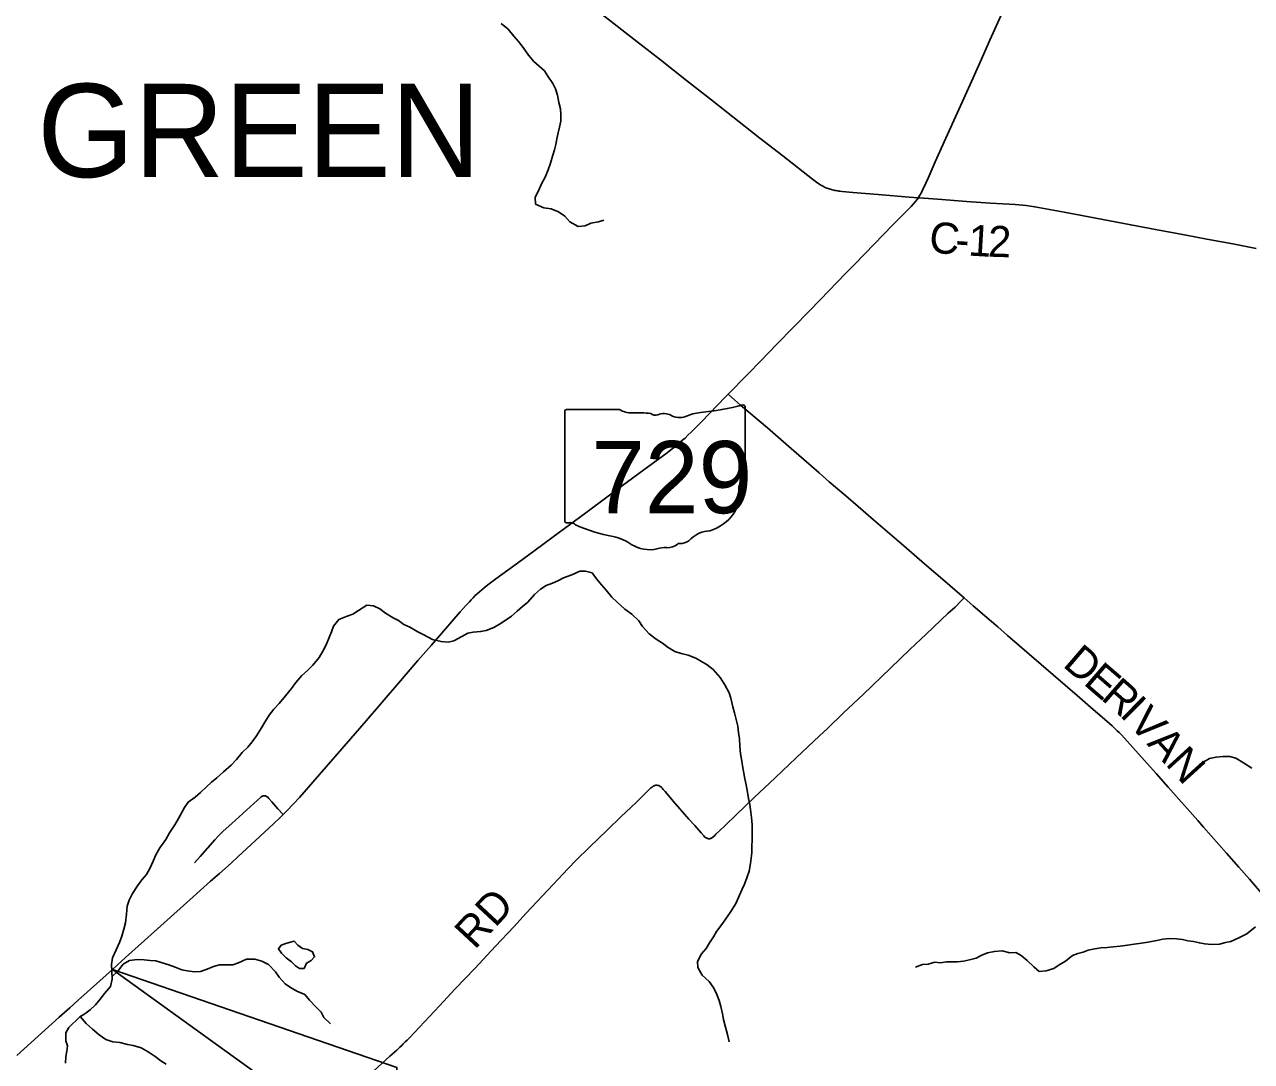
# Model space of a CAD drawing. Extents: x 0 to 34, y 0 to 22.
# Drawn here: x 25.971 to 28.213, y 15.082 to 16.977 of the extents above; entities that cross this region are included whole.
import ezdxf

# ---------------------------------------------------------------- set-up
doc = ezdxf.new("R2010")
doc.units = 0
for name, color, linetype in [('GM_X_County_Road', 7, 'Continuous'), ('GM_X_County_Road_Text', 7, 'Continuous'), ('GM_X_Minor_Lake', 7, 'Continuous'), ('GM_X_Minor_River', 7, 'Continuous'), ('GM_X_State_Location', 7, 'Continuous'), ('GM_X_State_Route', 7, 'Continuous'), ('GM_X_State_Shield', 7, 'Continuous'), ('GM_X_Township_Road', 7, 'Continuous'), ('GM_X_Township_Road_Text', 7, 'Continuous'), ('GM_X_Township_Text', 7, 'Continuous'), ('SH_Text', 7, 'Continuous')]:
    doc.layers.add(name, color=color, linetype=linetype)

msp = doc.modelspace()

# ---------------------------------------------------------------- linework, layer by layer
at = {"layer": 'GM_X_County_Road'}
for points in [[(27.6045, 16.66), (27.5878, 16.6613), (27.5315, 16.6661), (27.485, 16.67), (27.4654, 16.6718), (27.4615, 16.6722), (27.4595, 16.6725), (27.4577, 16.6727), (27.4548, 16.6732), (27.4525, 16.6736), (27.4519, 16.6737), (27.4504, 16.674), (27.4494, 16.6742), (27.4472, 16.6747), (27.4458, 16.6751), (27.4438, 16.6757), (27.4417, 16.6764), (27.4402, 16.6769), (27.4378, 16.6778), (27.4343, 16.6792), (27.4318, 16.6804), (27.4305, 16.6811), (27.4284, 16.6823), (27.4274, 16.6828), (27.426, 16.6837), (27.4211, 16.6871), (27.4112, 16.6944), (27.3568, 16.7369), (27.315, 16.7692), (27.2657, 16.8079), (27.2247, 16.8403), (27.1813, 16.8746), (27.1333, 16.912), (27.1148, 16.9267), (27.0957, 16.9416), (27.0157, 17.0038)], [(28.222, 16.5677), (28.1792, 16.5759), (28.1322, 16.5847), (28.0943, 16.5918), (28.0381, 16.6022), (27.9929, 16.6107), (27.9386, 16.6211), (27.8715, 16.6338), (27.8177, 16.6437), (27.8017, 16.6461), (27.7818, 16.648), (27.7365, 16.6506), (27.6925, 16.6535), (27.6479, 16.6568), (27.607, 16.6598), (27.6045, 16.66)], [(27.6882, 15.9292), (27.6805, 15.9359), (27.6533, 15.9596), (27.6161, 15.9916), (27.5785, 16.0242), (27.5525, 16.0463), (27.5229, 16.0718), (27.4946, 16.0961), (27.4721, 16.1157), (27.4419, 16.1415), (27.4232, 16.1579), (27.4049, 16.1739), (27.3678, 16.2059), (27.3288, 16.2396), (27.2795, 16.2815), (27.2632, 16.2958), (27.257, 16.3011)], [(28.2357, 15.3855), (28.2096, 15.4154), (28.1901, 15.4372), (28.1678, 15.4631), (28.1259, 15.5106), (28.1152, 15.5227), (28.0613, 15.5837), (28.0393, 15.6082), (27.9969, 15.6561), (27.9814, 15.6731), (27.9766, 15.6782), (27.9719, 15.6831), (27.9683, 15.6866), (27.9639, 15.6909), (27.9588, 15.6955), (27.9542, 15.6997), (27.9195, 15.7298), (27.8951, 15.751), (27.807, 15.8267), (27.7895, 15.8417), (27.7674, 15.8607), (27.7498, 15.8764), (27.7384, 15.8861), (27.7049, 15.9148), (27.6882, 15.9292)]]:
    msp.add_lwpolyline(points, dxfattribs=at)
at = {"layer": 'GM_X_Minor_Lake'}
for points in [[(26.4925, 15.285), (26.4889, 15.2867), (26.4794, 15.2887), (26.4707, 15.2945), (26.464, 15.3018), (26.4548, 15.2996), (26.4491, 15.2977), (26.4404, 15.2948), (26.4354, 15.288), (26.441, 15.28), (26.4493, 15.2715), (26.4595, 15.2646)], [(26.4595, 15.2646), (26.4666, 15.257), (26.4741, 15.252), (26.4821, 15.2523), (26.4867, 15.2617), (26.4951, 15.2669), (26.5013, 15.2733), (26.4979, 15.2825), (26.4925, 15.285)]]:
    msp.add_lwpolyline(points, dxfattribs=at)
at = {"layer": 'GM_X_Minor_River'}
for points in [[(26.8426, 16.9788), (26.8551, 16.968), (26.8656, 16.9554), (26.8738, 16.9454), (26.8828, 16.9347), (26.8926, 16.9209), (26.9023, 16.909), (26.9213, 16.892)], [(26.9213, 16.892), (26.9276, 16.8826), (26.937, 16.8692), (26.9414, 16.8593), (26.9455, 16.8475), (26.9477, 16.8345), (26.9506, 16.8228), (26.9516, 16.8121), (26.9512, 16.8004), (26.9492, 16.7894), (26.9464, 16.7788), (26.9444, 16.7678), (26.942, 16.7576), (26.9397, 16.7477), (26.9369, 16.7379), (26.9326, 16.7235), (26.928, 16.711), (26.9229, 16.6978), (26.9163, 16.6857), (26.9105, 16.6728), (26.9047, 16.6615), (26.9054, 16.6486), (26.9205, 16.642), (26.9338, 16.64), (26.9474, 16.6342), (26.9587, 16.6265), (26.9677, 16.6161), (26.9828, 16.6076), (26.9961, 16.6087), (27.0064, 16.6135), (27.0204, 16.6164), (27.03, 16.6194)], [(26.4107, 15.7023), (26.4184, 15.7151), (26.4272, 15.726), (26.4368, 15.7362), (26.4483, 15.7501), (26.4591, 15.7637), (26.4671, 15.7746), (26.4782, 15.7874), (26.4882, 15.7965), (26.4982, 15.8062), (26.51, 15.8202), (26.5166, 15.8319), (26.5224, 15.8432), (26.5278, 15.8568), (26.5321, 15.8674), (26.536, 15.8776), (26.5456, 15.8897), (26.5608, 15.8956), (26.5715, 15.8997), (26.5814, 15.9061), (26.5967, 15.9158), (26.6092, 15.9149), (26.6205, 15.9091), (26.6311, 15.9015), (26.645, 15.8926), (26.6548, 15.888), (26.6646, 15.8803), (26.6756, 15.8756), (26.6899, 15.8675), (26.7001, 15.8625), (26.7171, 15.8532), (26.7327, 15.8493), (26.7456, 15.8484), (26.7558, 15.851), (26.7703, 15.8588), (26.7814, 15.8648), (26.7909, 15.8666), (26.8049, 15.8676), (26.8152, 15.8694), (26.8289, 15.8754), (26.8392, 15.881), (26.8499, 15.8877), (26.861, 15.896), (26.8717, 15.905), (26.8816, 15.9132), (26.8912, 15.9215), (26.9034, 15.9351), (26.9141, 15.9452), (26.9245, 15.9519), (26.9363, 15.9564), (26.9458, 15.9605), (26.9565, 15.9657), (26.9713, 15.9716), (26.9862, 15.978), (26.9964, 15.9779), (27.0085, 15.9747), (27.0168, 15.964), (27.0258, 15.9533), (27.034, 15.9434), (27.0449, 15.9307), (27.0543, 15.9212), (27.0686, 15.9089), (27.0814, 15.8993), (27.0942, 15.887), (27.1006, 15.8767), (27.1126, 15.8637), (27.1254, 15.8541), (27.1371, 15.8468), (27.1477, 15.8384), (27.1598, 15.831), (27.1715, 15.8275), (27.1844, 15.8244), (27.1983, 15.8189), (27.2082, 15.8128), (27.2187, 15.807), (27.2297, 15.7981), (27.2424, 15.784), (27.2514, 15.7702), (27.2589, 15.7558), (27.2618, 15.7462), (27.2658, 15.7299), (27.2688, 15.7192), (27.2724, 15.7048), (27.2746, 15.6949), (27.276, 15.6835), (27.2778, 15.6717), (27.2788, 15.6584), (27.2799, 15.6444), (27.282, 15.6307), (27.2842, 15.6189), (27.2856, 15.609), (27.2874, 15.5984), (27.29, 15.5877), (27.2925, 15.5744), (27.2943, 15.5626), (27.2965, 15.552), (27.2983, 15.5425), (27.3, 15.528), (27.3011, 15.5144), (27.3013, 15.5015), (27.3012, 15.4886)], [(26.0464, 15.079), (26.0466, 15.0915), (26.0485, 15.1013), (26.0498, 15.1108), (26.0468, 15.1203), (26.0466, 15.1347), (26.0524, 15.1446), (26.0723, 15.1641), (26.0818, 15.1693), (26.0914, 15.1768), (26.1009, 15.1859), (26.1094, 15.196), (26.1178, 15.2062), (26.1282, 15.219), (26.1317, 15.2327), (26.1307, 15.2478), (26.1301, 15.2596), (26.1324, 15.2717), (26.1386, 15.2861), (26.1448, 15.2997), (26.1491, 15.3111), (26.153, 15.3243), (26.1558, 15.3357), (26.1574, 15.3516), (26.1591, 15.366), (26.1626, 15.377), (26.1688, 15.3894), (26.1776, 15.403), (26.1857, 15.414), (26.1942, 15.4238), (26.2003, 15.4351), (26.2065, 15.4483), (26.2112, 15.46), (26.2185, 15.4729), (26.2293, 15.4876), (26.2362, 15.4997), (26.2462, 15.5144), (26.2528, 15.5261), (26.2636, 15.5465), (26.2701, 15.5563), (26.2831, 15.5649), (26.2927, 15.5739), (26.303, 15.5833), (26.3129, 15.5923), (26.3229, 15.6006), (26.3347, 15.6115), (26.3489, 15.6239), (26.3585, 15.6337), (26.3688, 15.6469), (26.3795, 15.6563), (26.3876, 15.6661), (26.3953, 15.6774), (26.4041, 15.6921), (26.4107, 15.7023)], [(28.2142, 15.6181), (28.1991, 15.6278), (28.1852, 15.6366), (28.1742, 15.6394), (28.1617, 15.6395), (28.1487, 15.6385), (28.137, 15.6355), (28.1232, 15.6281)], [(27.3012, 15.4886), (27.3007, 15.4741), (27.3002, 15.4635), (27.2994, 15.4537), (27.2981, 15.4438), (27.2954, 15.4298), (27.2911, 15.4177), (27.2868, 15.4063), (27.2821, 15.3957), (27.276, 15.3821), (27.2713, 15.3708), (27.2632, 15.358), (27.2544, 15.3448), (27.2436, 15.3304), (27.2359, 15.3199), (27.2301, 15.3101), (27.2232, 15.2991), (27.2167, 15.2889), (27.2086, 15.2787), (27.2009, 15.2652), (27.2016, 15.2541), (27.2098, 15.24), (27.2226, 15.2285), (27.2297, 15.2182), (27.2353, 15.2079), (27.2408, 15.1938), (27.2438, 15.1828), (27.2471, 15.1695), (27.2489, 15.1592), (27.2522, 15.1451), (27.2558, 15.1318), (27.2588, 15.1181)], [(28.221, 15.3285), (28.205, 15.3157), (28.1905, 15.3083), (28.1757, 15.3016), (28.1661, 15.2994), (28.1551, 15.2964), (28.1407, 15.2958), (28.1282, 15.2971), (28.1183, 15.299), (28.1077, 15.3014), (28.0975, 15.303), (28.0877, 15.305), (28.0763, 15.3063), (28.0634, 15.3071), (28.0516, 15.3057), (28.0406, 15.3035), (28.0242, 15.3003), (28.0128, 15.2985), (27.9992, 15.2967), (27.987, 15.2949), (27.9737, 15.2931), (27.9608, 15.2917)], [(27.9608, 15.2917), (27.9498, 15.2907), (27.9384, 15.2897), (27.9274, 15.2879), (27.9152, 15.2857), (27.9057, 15.282), (27.8962, 15.2794), (27.8867, 15.2757), (27.8737, 15.2656), (27.8618, 15.2588), (27.8523, 15.2521), (27.8382, 15.2477), (27.8257, 15.2466), (27.8155, 15.2555), (27.8035, 15.2666), (27.7929, 15.2758), (27.7827, 15.2812), (27.7717, 15.2809), (27.7581, 15.2844), (27.7437, 15.2834), (27.7308, 15.2809), (27.7208, 15.2764), (27.7106, 15.2708), (27.698, 15.2679), (27.687, 15.2653), (27.6763, 15.2643), (27.6657, 15.2644), (27.6562, 15.2641), (27.6452, 15.2623), (27.6346, 15.2635), (27.6224, 15.2599), (27.6125, 15.2592), (27.5996, 15.2547)], [(26.1314, 15.2375), (26.1421, 15.247), (26.1517, 15.2602), (26.1631, 15.2665), (26.1776, 15.2687), (26.1897, 15.2682), (26.2011, 15.2669), (26.2113, 15.2661), (26.2212, 15.2633), (26.2351, 15.2587), (26.2465, 15.2548), (26.2586, 15.2497), (26.2688, 15.2477), (26.2821, 15.2461), (26.2927, 15.2464), (26.3053, 15.2508), (26.3167, 15.256), (26.3277, 15.259), (26.3387, 15.2589), (26.352, 15.2591), (26.3623, 15.2628), (26.3772, 15.2691), (26.3923, 15.269), (26.4048, 15.2655), (26.4169, 15.2593), (26.4301, 15.2463), (26.4368, 15.2363), (26.4477, 15.2241), (26.4575, 15.2172), (26.4688, 15.211), (26.4836, 15.2048), (26.4922, 15.1945), (26.5042, 15.1818), (26.5136, 15.1723), (26.5185, 15.1627), (26.5305, 15.1512)], [(26.0731, 15.1646), (26.0843, 15.1515), (26.0956, 15.1411), (26.108, 15.1308), (26.1201, 15.1223), (26.1326, 15.1184), (26.1458, 15.1171), (26.1595, 15.1136), (26.1697, 15.1112), (26.1844, 15.1073), (26.1973, 15.1), (26.2101, 15.0911), (26.2203, 15.0835), (26.2301, 15.0773)]]:
    msp.add_lwpolyline(points, dxfattribs=at)
at = {"layer": 'GM_X_State_Route'}
msp.add_lwpolyline([(25.9573, 15.0931), (26.0348, 15.163), (26.0541, 15.1805), (26.0694, 15.1942), (26.1092, 15.2299), (26.1322, 15.2504), (26.1561, 15.2721), (26.1906, 15.3035), (26.2268, 15.3357), (26.2734, 15.3776), (26.3114, 15.4115), (26.3276, 15.426), (26.3491, 15.4448), (26.3618, 15.4567), (26.393, 15.4851), (26.4271, 15.5168), (26.4374, 15.5267), (26.4438, 15.5332), (26.4514, 15.5409), (26.4736, 15.5644), (26.4981, 15.5925), (26.5226, 15.6205), (26.551, 15.6534), (26.584, 15.6914), (26.6144, 15.7267), (26.6324, 15.7473), (26.651, 15.769), (26.6902, 15.8147), (26.7143, 15.8423), (26.7677, 15.9037), (26.7787, 15.9159), (26.7843, 15.9222), (26.7876, 15.9257), (26.7911, 15.9293), (26.7945, 15.9327), (26.7991, 15.9371), (26.8028, 15.9403), (26.807, 15.944), (26.8113, 15.9475), (26.8181, 15.9529), (26.8325, 15.9638), (26.8657, 15.9878), (26.9018, 16.0143), (26.9373, 16.0405), (26.9972, 16.0848), (27.0381, 16.1151), (27.0641, 16.1344), (27.1031, 16.1631), (27.1457, 16.1944), (27.1526, 16.1996), (27.1591, 16.2046), (27.1642, 16.2088), (27.1696, 16.2134), (27.1744, 16.2177), (27.1784, 16.2213), (27.1837, 16.2263), (27.1896, 16.232), (27.2084, 16.251), (27.2526, 16.2965), (27.257, 16.3011), (27.2924, 16.3375), (27.3173, 16.3627), (27.3463, 16.3926), (27.4056, 16.4536), (27.4256, 16.474), (27.4721, 16.5224), (27.4873, 16.5379), (27.5069, 16.558), (27.558, 16.6105), (27.5764, 16.629), (27.583, 16.6356), (27.5878, 16.6405), (27.5916, 16.6445), (27.5959, 16.6491), (27.5993, 16.6533), (27.6023, 16.6568), (27.6045, 16.66), (27.6049, 16.6606), (27.6077, 16.6652), (27.6102, 16.6698), (27.6124, 16.6741), (27.6183, 16.6871), (27.6224, 16.6962), (27.6357, 16.7257), (27.6549, 16.7688), (27.6994, 16.8673), (27.7174, 16.9076), (27.7354, 16.9479), (27.7845, 17.058)], dxfattribs=at)
at = {"layer": 'GM_X_State_Shield'}
for p, q in [((27.2882, 16.1736), (27.2882, 16.2783)), ((26.9587, 16.2699), (26.9587, 16.0698)), ((27.0584, 16.2734), (26.9619, 16.2734)), ((27.2882, 16.1737), (27.2882, 16.1736))]:
    msp.add_line(p, q, dxfattribs=at)
for centre, major_axis, start_param, end_param in [((27.1708, 16.5462), (0.3495, 0), 4.814394, 5.042369), ((27.2846, 16.2788), (0.00367, 0), 6.141152, 7.989035), ((26.9624, 16.2704), (0.00382, 0), 1.712693, 3.28349), ((27.0814, 16.2966), (0.037, 0), 4.042523, 4.731795), ((27.0937, 16.161), (0.133, 0), 1.404758, 1.657858), ((27.1239, 16.2714), (0.0107, 0), 3.836095, 5.185415), ((27.1396, 16.2483), (0.0222, 0), 0.950623, 2.079405), ((27.1682, 16.28), (0.0267, 0), 4.081561, 5.145723), ((27.2154, 16.2122), (0.0703, 0), 1.699011, 2.107814), ((27.2874, 16.166), (0.00568, 0), 1.883978, 3.671073), ((27.2843, 16.1732), (0.00393, 0), 5.05454, 6.418171), ((27.3014, 16.1298), (0.0248, 0), 2.387724, 3.262537), ((27.2513, 16.1527), (0.0341, 0), 5.934695, 6.695948), ((27.1904, 16.1165), (0.0874, 0), 5.101752, 6.440018), ((26.9625, 16.0694), (0.00385, 0), 3.00124, 4.508301), ((26.9631, 16.0898), (0.0294, 0), 4.665946, 4.897461), ((26.9691, 16.0583), (0.0106, 0), 0.519207, 1.627899), ((27.1029, 16.2381), (0.2524, 0), 4.195997, 4.488961), ((27.0276, 15.9799), (0.079, 0), 0.823519, 1.323587), ((27.1666, 16.0504), (0.0282, 0), 4.937069, 5.64225), ((27.2273, 16.0136), (0.0479, 0), 1.647645, 2.488434), ((27.1131, 16.0573), (0.0501, 0), 4.026481, 4.996735), ((27.142, 15.9881), (0.0412, 0), 1.495662, 1.94098), ((27.1457, 16.0423), (0.0267, 0), 4.691044, 5.507374), ((27.1698, 16.0229), (0.00752, 0), 1.147584, 2.315152)]:
    msp.add_ellipse(centre, major_axis=major_axis, ratio=0.8, start_param=start_param, end_param=end_param, dxfattribs=at)
at = {"layer": 'GM_X_Township_Road'}
for points in [[(26.6097, 15.0654), (26.6392, 15.092), (26.6517, 15.1032), (26.6541, 15.1054), (26.6572, 15.1084), (26.6607, 15.1117), (26.6634, 15.1145), (26.6668, 15.1179), (26.6703, 15.1214), (26.6747, 15.1258), (26.7298, 15.184), (26.7586, 15.2149), (26.794, 15.2523), (26.8318, 15.2927), (26.8654, 15.3284), (26.8881, 15.3532), (26.9373, 15.4058), (26.9646, 15.4348), (26.9794, 15.4498), (27.0033, 15.4733), (27.0364, 15.5052), (27.0619, 15.5298), (27.0884, 15.5551), (27.1013, 15.5677), (27.1074, 15.5739), (27.1141, 15.5804), (27.1161, 15.582), (27.1181, 15.5836), (27.1201, 15.585), (27.1219, 15.5861), (27.1231, 15.5864), (27.1248, 15.5868), (27.1267, 15.5868), (27.1289, 15.5866), (27.1306, 15.5862), (27.1318, 15.5856), (27.133, 15.5849), (27.1345, 15.5838), (27.1356, 15.5826), (27.1366, 15.5815), (27.1386, 15.5792), (27.1419, 15.5754), (27.1569, 15.5579), (27.1856, 15.5252), (27.1962, 15.5131), (27.2076, 15.4999), (27.2126, 15.4943), (27.2148, 15.4922), (27.2159, 15.4914), (27.2169, 15.4907), (27.218, 15.4901), (27.2192, 15.4897), (27.2203, 15.4894), (27.2217, 15.4891), (27.2228, 15.4891), (27.2244, 15.4894), (27.2255, 15.4897), (27.2268, 15.4904), (27.2289, 15.4919), (27.2326, 15.4952), (27.2348, 15.4974), (27.242, 15.5043), (27.2511, 15.5128), (27.2725, 15.5336), (27.3048, 15.5645), (27.3433, 15.6007), (27.3814, 15.6372), (27.424, 15.6771), (27.4385, 15.6907), (27.4681, 15.7191), (27.5036, 15.753), (27.5543, 15.8015), (27.5894, 15.8349), (27.6191, 15.8632), (27.6458, 15.8884), (27.6594, 15.9011), (27.6718, 15.9124), (27.6831, 15.924), (27.6882, 15.9292)], [(26.2822, 15.4449), (26.2922, 15.4568), (26.3189, 15.487), (26.3261, 15.4947), (26.3345, 15.5029), (26.35, 15.5171), (26.3969, 15.5597), (26.4024, 15.5646), (26.4036, 15.5655), (26.4049, 15.5663), (26.4061, 15.5669), (26.4074, 15.5674), (26.4085, 15.5677), (26.4096, 15.5677), (26.4106, 15.5676), (26.4118, 15.5674), (26.4128, 15.567), (26.4138, 15.5665), (26.4147, 15.5659), (26.4157, 15.5651), (26.4179, 15.563), (26.4231, 15.5569), (26.4345, 15.5438), (26.4438, 15.5332)]]:
    msp.add_lwpolyline(points, dxfattribs=at)
at = {"layer": 'SH_Text'}
msp.add_lwpolyline([(26.1322, 15.2504), (26.6515, 15.0716), (26.6515, 14.876)], close=True, dxfattribs=at)

# ---------------------------------------------------------------- texts
at = {"layer": 'GM_X_County_Road_Text'}
for s, rotation, p in [('C', 354.6999, (27.6229, 16.5607)), ('1', 356.6813, (27.6948, 16.5547)), ('2', 358.2117, (27.7314, 16.5526)), ('-', 356.2509, (27.6711, 16.5562)), ('D', 319.249, (27.8667, 15.8053)), ('E', 319.2342, (27.9045, 15.7726)), ('R', 318.7146, (27.9366, 15.745)), ('I', 315.4747, (27.9711, 15.7148)), ('V', 312.7224, (27.9872, 15.6989)), ('A', 312.2815, (28.021, 15.6623)), ('N', 312.2737, (28.0547, 15.6253))]:
    msp.add_text(s, height=0.0568, rotation=rotation, dxfattribs=at).set_placement(p)
at = {"layer": 'GM_X_State_Location'}
for s in ['s', 'r']:
    msp.add_text(s, height=0.000189, dxfattribs=at).set_placement((27.1197, 16.1566))
msp.add_text('729', height=0.000189, rotation=0, dxfattribs=at).set_placement((27.0529, 16.1428))
at = {"layer": 'GM_X_State_Shield'}
msp.add_text('729', height=0.13184, dxfattribs=at).set_placement((27.0071, 16.0839))
at = {"layer": 'GM_X_Township_Road_Text'}
msp.add_text('RD', height=0.05682, rotation=47.0955, dxfattribs=at).set_placement((26.794, 15.2852))
at = {"layer": 'GM_X_Township_Text'}
msp.add_text('GREEN', height=0.17045, rotation=0, dxfattribs=at).set_placement((25.9946, 16.6979))

doc.saveas('drawing.dxf')
